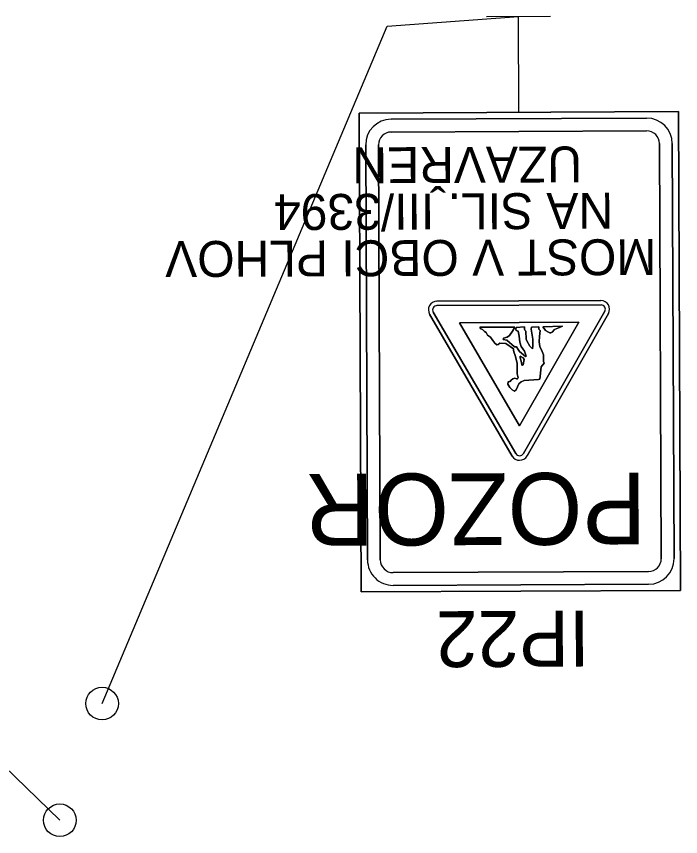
# Model space of a CAD drawing. Extents: x -688893 to -679983, y -1088371 to -1075771.
# Drawn here: x -686022 to -685398, y -1077861 to -1077090 of the extents above; entities that cross this region are included whole.
import ezdxf

# ---------------------------------------------------------------- set-up
doc = ezdxf.new("R2010")
doc.units = 0
for name, color, linetype in [('SDZ', 7, 'Continuous'), ('SDZ ozn', 7, 'Continuous'), ('SDZ plochy', 7, 'Continuous'), ('SDZ symbol', 7, 'Continuous')]:
    doc.layers.add(name, color=color, linetype=linetype)

msp = doc.modelspace()

# ---------------------------------------------------------------- linework, layer by layer
at = {"layer": 'SDZ'}
for p, q in [((-685520.53, -1077089.96), (-685580.53, -1077090.22)), ((-685550.14, -1077180.09), (-685550.53, -1077090.09)), ((-685700.14, -1077180.75), (-685400.14, -1077179.43)), ((-685698.17, -1077630.74), (-685700.14, -1077180.75)), ((-685670.11, -1077186.62), (-685430.11, -1077185.57)), ((-685400.14, -1077179.43), (-685398.17, -1077629.43)), ((-685670.06, -1077198.62), (-685430.06, -1077197.57)), ((-685692.3, -1077600.72), (-685694.01, -1077210.72)), ((-685680.3, -1077600.66), (-685682.01, -1077210.67)), ((-685418.01, -1077209.51), (-685416.3, -1077599.51)), ((-685406.01, -1077209.46), (-685404.3, -1077599.46)), ((-685472.92, -1077361.01), (-685627.1, -1077361.69)), ((-685473.01, -1077356.96), (-685627.05, -1077357.64)), ((-685556.41, -1077503.05), (-685634.01, -1077369.81)), ((-685630.58, -1077367.78), (-685552.91, -1077500.78)), ((-685545.89, -1077500.74), (-685469.39, -1077367.07)), ((-685465.94, -1077369.08), (-685542.37, -1077502.99)), ((-685493.85, -1077377.3), (-685606.03, -1077377.79)), ((-685606.03, -1077377.79), (-685549.52, -1077474.55)), ((-685549.52, -1077474.55), (-685493.85, -1077377.3)), ((-685553.97, -1077382.02), (-685586.78, -1077381.96)), ((-685586.78, -1077381.96), (-685585.96, -1077383.58)), ((-685585.96, -1077383.58), (-685584.13, -1077384.18)), ((-685584.13, -1077384.18), (-685582.51, -1077385.99)), ((-685582.51, -1077385.99), (-685580.88, -1077387)), ((-685558.8, -1077389.94), (-685556.18, -1077385.88)), ((-685556.18, -1077385.88), (-685553.97, -1077382.02)), ((-685552.55, -1077382.22), (-685552.95, -1077383.84)), ((-685552.95, -1077383.84), (-685552.74, -1077385.05)), ((-685552.74, -1077385.05), (-685550.71, -1077385.85)), ((-685544.86, -1077381.58), (-685552.55, -1077382.22)), ((-685550.71, -1077385.85), (-685549.88, -1077390.51)), ((-685544.85, -1077383.8), (-685544.86, -1077381.58)), ((-685544.64, -1077384.82), (-685544.85, -1077383.8)), ((-685543.42, -1077385.82), (-685544.64, -1077384.82)), ((-685543.39, -1077393.32), (-685543.42, -1077385.82)), ((-685538.18, -1077381.95), (-685538.57, -1077383.78)), ((-685538.57, -1077383.78), (-685536.91, -1077393.29)), ((-685531.49, -1077381.72), (-685538.18, -1077381.95)), ((-685531.28, -1077383.74), (-685531.49, -1077381.72)), ((-685530.06, -1077384.95), (-685531.28, -1077383.74)), ((-685530.85, -1077390.63), (-685530.06, -1077384.95)), ((-685509.02, -1077381.01), (-685527.65, -1077381.5)), ((-685527.65, -1077381.5), (-685526.43, -1077383.12)), ((-685526.43, -1077383.12), (-685525, -1077385.13)), ((-685525, -1077385.13), (-685522.16, -1077386.54)), ((-685518.92, -1077386.73), (-685516.5, -1077384.08)), ((-685516.5, -1077384.08), (-685513.47, -1077382.86)), ((-685513.47, -1077382.86), (-685509.02, -1077381.01)), ((-685580.88, -1077387), (-685579.45, -1077389.42)), ((-685579.45, -1077389.42), (-685576.81, -1077391.44)), ((-685576.81, -1077391.44), (-685574.57, -1077394.46)), ((-685564.85, -1077393.61), (-685564.46, -1077392.19)), ((-685561.41, -1077394.2), (-685564.85, -1077393.61)), ((-685564.46, -1077392.19), (-685561.22, -1077391.37)), ((-685554.09, -1077400.45), (-685561.41, -1077394.2)), ((-685561.22, -1077391.37), (-685558.8, -1077389.94)), ((-685549.88, -1077390.51), (-685549.25, -1077395.97)), ((-685542.57, -1077394.73), (-685543.39, -1077393.32)), ((-685536.91, -1077393.29), (-685536.88, -1077399.36)), ((-685531.03, -1077395.69), (-685530.85, -1077390.63)), ((-685522.16, -1077386.54), (-685521.14, -1077387.14)), ((-685521.14, -1077387.14), (-685519.93, -1077387.14)), ((-685519.93, -1077387.14), (-685518.92, -1077386.73)), ((-685574.57, -1077394.46), (-685572.53, -1077397.09)), ((-685572.53, -1077397.09), (-685570.91, -1077398.7)), ((-685570.91, -1077398.7), (-685569.69, -1077398.29)), ((-685569.69, -1077398.29), (-685568.08, -1077396.87)), ((-685568.08, -1077396.87), (-685562.41, -1077397.25)), ((-685562.41, -1077397.25), (-685555.1, -1077402.28)), ((-685552.47, -1077400.44), (-685554.09, -1077400.45)), ((-685550.64, -1077402.86), (-685552.47, -1077400.44)), ((-685549.25, -1077395.97), (-685547.82, -1077400.22)), ((-685547.82, -1077400.22), (-685544.76, -1077404.66)), ((-685539.72, -1077399.78), (-685542.57, -1077394.73)), ((-685537.28, -1077402.4), (-685539.72, -1077399.78)), ((-685536.88, -1077399.36), (-685537.28, -1077402.4)), ((-685530.4, -1077400.14), (-685531.03, -1077395.69)), ((-685528.35, -1077404.99), (-685530.4, -1077400.14)), ((-685555.1, -1077402.28), (-685555.29, -1077403.49)), ((-685555.29, -1077403.49), (-685554.68, -1077405.11)), ((-685554.68, -1077405.11), (-685553.45, -1077408.55)), ((-685553.45, -1077408.55), (-685551.8, -1077415.83)), ((-685549.42, -1077404.68), (-685550.64, -1077402.86)), ((-685543.72, -1077409.52), (-685549.42, -1077404.68)), ((-685548.79, -1077409.13), (-685548.78, -1077410.75)), ((-685546.15, -1077410.74), (-685548.79, -1077409.13)), ((-685544.76, -1077404.66), (-685543.32, -1077409.11)), ((-685543.32, -1077409.11), (-685543.72, -1077409.52)), ((-685526.92, -1077408.03), (-685528.35, -1077404.99)), ((-685527.1, -1077414.3), (-685526.92, -1077408.03)), ((-685551.8, -1077415.83), (-685551.57, -1077422.11)), ((-685548.78, -1077410.75), (-685547.96, -1077413.99)), ((-685547.96, -1077413.99), (-685547.34, -1077417.03)), ((-685547.34, -1077417.03), (-685546.73, -1077418.04)), ((-685545.13, -1077412.36), (-685546.15, -1077410.74)), ((-685545.92, -1077417.42), (-685545.33, -1077413.78)), ((-685545.33, -1077413.78), (-685545.13, -1077412.36)), ((-685529.1, -1077419.17), (-685526.28, -1077415.72)), ((-685526.28, -1077415.72), (-685527.1, -1077414.3)), ((-685551.57, -1077422.11), (-685551.55, -1077425.95)), ((-685546.73, -1077418.04), (-685545.92, -1077417.42)), ((-685530.27, -1077430.72), (-685529.1, -1077419.17)), ((-685557.2, -1077431.65), (-685558.2, -1077433.07)), ((-685555.78, -1077430.43), (-685557.2, -1077431.65)), ((-685553.96, -1077430.01), (-685555.78, -1077430.43)), ((-685552.34, -1077430.61), (-685553.96, -1077430.01)), ((-685551.53, -1077430.61), (-685552.34, -1077430.61)), ((-685551.55, -1077425.95), (-685551.13, -1077428.38)), ((-685550.73, -1077429.39), (-685551.53, -1077430.61)), ((-685551.13, -1077428.38), (-685550.73, -1077429.39)), ((-685548.08, -1077433.23), (-685545.25, -1077432.2)), ((-685545.25, -1077432.2), (-685531.68, -1077431.13)), ((-685531.68, -1077431.13), (-685530.27, -1077430.72)), ((-685560.23, -1077433.48), (-685560.42, -1077435.51)), ((-685560.42, -1077435.51), (-685558.58, -1077438.54)), ((-685559.22, -1077432.87), (-685560.23, -1077433.48)), ((-685558.2, -1077433.07), (-685559.22, -1077432.87)), ((-685558.58, -1077438.54), (-685556.34, -1077440.96)), ((-685552.7, -1077440.94), (-685551.29, -1077438.1)), ((-685551.29, -1077438.1), (-685550.09, -1077435.06)), ((-685550.09, -1077435.06), (-685548.08, -1077433.23)), ((-685556.34, -1077440.96), (-685554.32, -1077441.96)), ((-685554.32, -1077441.96), (-685552.7, -1077440.94)), ((-685545.96, -1077500.85), (-685545.96, -1077500.85)), ((-685556.48, -1077502.93), (-685556.48, -1077502.93)), ((-685428.25, -1077611.56), (-685668.25, -1077612.61)), ((-685428.2, -1077623.56), (-685668.19, -1077624.61)), ((-685398.17, -1077629.43), (-685698.17, -1077630.74))]:
    msp.add_line(p, q, dxfattribs=at)
for points in [[(-685941.66, -1077735.65), (-685673.9, -1077099.13), (-685550.53, -1077090.09)], [(-685981.36, -1077845.3), (-686201.95, -1077631.56), (-686300.88, -1077632.7)]]:
    msp.add_lwpolyline(points, dxfattribs=at)
for centre in [(-685941.66, -1077735.65), (-685981.36, -1077845.3)]:
    msp.add_circle(centre, 15.36, dxfattribs=at)
for centre, radius, start, end in [((-685430.01, -1077209.57), 24, 0.25087, 90.25087), ((-685670.01, -1077210.62), 24, 90.25087, 180.25087), ((-685670.01, -1077210.62), 12, 90.25087, 180.25087), ((-685430.01, -1077209.57), 12, 0.25087, 90.25087), ((-685627.02, -1077365.74), 8.1, 90.25087, 210.21996), ((-685627.08, -1077365.74), 4.05, 90.25087, 210.28517), ((-685472.97, -1077365.06), 8.1, 330.28177, 90.25087), ((-685472.91, -1077365.06), 4.05, 330.21657, 90.25087), ((-685549.41, -1077498.73), 4.05, 210.28517, 330.21657), ((-685549.41, -1077498.97), 8.1, 210.21996, 330.28177), ((-685668.3, -1077600.61), 24, 180.25087, 270.25087), ((-685668.3, -1077600.61), 12, 180.25087, 270.25087), ((-685428.3, -1077599.56), 12, 270.25087, 0.25087), ((-685428.3, -1077599.56), 24, 270.25087, 0.25087)]:
    msp.add_arc(centre, radius, start, end, dxfattribs=at)
at = {"layer": 'SDZ plochy'}
for p, q in [((-685400.14, -1077179.43), (-685700.14, -1077180.75)), ((-685700.14, -1077180.75), (-685698.17, -1077630.74)), ((-685430.11, -1077185.57), (-685670.11, -1077186.62)), ((-685670.11, -1077186.62), (-685430.11, -1077185.57)), ((-685398.17, -1077629.43), (-685400.14, -1077179.43)), ((-685670.06, -1077198.62), (-685430.06, -1077197.57)), ((-685430.06, -1077197.57), (-685670.06, -1077198.62)), ((-685694.01, -1077210.72), (-685692.3, -1077600.72)), ((-685692.3, -1077600.72), (-685694.01, -1077210.72)), ((-685680.3, -1077600.66), (-685682.01, -1077210.67)), ((-685682.01, -1077210.67), (-685680.3, -1077600.66)), ((-685418.01, -1077209.51), (-685416.3, -1077599.51)), ((-685416.3, -1077599.51), (-685418.01, -1077209.51)), ((-685404.3, -1077599.46), (-685406.01, -1077209.46)), ((-685406.01, -1077209.46), (-685404.3, -1077599.46)), ((-685472.92, -1077361.01), (-685627.1, -1077361.69)), ((-685627.1, -1077361.69), (-685472.92, -1077361.01)), ((-685627.05, -1077357.64), (-685473.01, -1077356.96)), ((-685473.01, -1077356.96), (-685627.05, -1077357.64)), ((-685556.41, -1077503.05), (-685634.01, -1077369.81)), ((-685634.01, -1077369.81), (-685556.41, -1077503.05)), ((-685630.58, -1077367.78), (-685552.91, -1077500.78)), ((-685552.91, -1077500.78), (-685630.58, -1077367.78)), ((-685545.89, -1077500.74), (-685469.39, -1077367.07)), ((-685469.39, -1077367.07), (-685545.89, -1077500.74)), ((-685465.94, -1077369.08), (-685542.37, -1077502.99)), ((-685542.37, -1077502.99), (-685465.94, -1077369.08)), ((-685606.03, -1077377.79), (-685493.85, -1077377.3)), ((-685493.85, -1077377.3), (-685606.03, -1077377.79)), ((-685549.52, -1077474.55), (-685606.03, -1077377.79)), ((-685606.03, -1077377.79), (-685549.52, -1077474.55)), ((-685493.85, -1077377.3), (-685549.52, -1077474.55)), ((-685549.52, -1077474.55), (-685493.85, -1077377.3)), ((-685553.97, -1077382.02), (-685586.78, -1077381.96)), ((-685586.78, -1077381.96), (-685585.96, -1077383.58)), ((-685585.96, -1077383.58), (-685586.78, -1077381.96)), ((-685586.78, -1077381.96), (-685553.97, -1077382.02)), ((-685585.96, -1077383.58), (-685584.13, -1077384.18)), ((-685584.13, -1077384.18), (-685585.96, -1077383.58)), ((-685584.13, -1077384.18), (-685582.51, -1077385.99)), ((-685582.51, -1077385.99), (-685584.13, -1077384.18)), ((-685582.51, -1077385.99), (-685580.88, -1077387)), ((-685580.88, -1077387), (-685582.51, -1077385.99)), ((-685558.8, -1077389.94), (-685556.18, -1077385.88)), ((-685556.18, -1077385.88), (-685558.8, -1077389.94)), ((-685556.18, -1077385.88), (-685553.97, -1077382.02)), ((-685553.97, -1077382.02), (-685556.18, -1077385.88)), ((-685552.55, -1077382.22), (-685552.95, -1077383.84)), ((-685552.95, -1077383.84), (-685552.55, -1077382.22)), ((-685552.95, -1077383.84), (-685552.74, -1077385.05)), ((-685552.74, -1077385.05), (-685552.95, -1077383.84)), ((-685552.74, -1077385.05), (-685550.71, -1077385.85)), ((-685550.71, -1077385.85), (-685552.74, -1077385.05)), ((-685544.86, -1077381.58), (-685552.55, -1077382.22)), ((-685552.55, -1077382.22), (-685544.86, -1077381.58)), ((-685550.71, -1077385.85), (-685549.88, -1077390.51)), ((-685549.88, -1077390.51), (-685550.71, -1077385.85)), ((-685544.85, -1077383.8), (-685544.86, -1077381.58)), ((-685544.86, -1077381.58), (-685544.85, -1077383.8)), ((-685544.64, -1077384.82), (-685544.85, -1077383.8)), ((-685544.85, -1077383.8), (-685544.64, -1077384.82)), ((-685543.42, -1077385.82), (-685544.64, -1077384.82)), ((-685544.64, -1077384.82), (-685543.42, -1077385.82)), ((-685543.39, -1077393.32), (-685543.42, -1077385.82)), ((-685543.42, -1077385.82), (-685543.39, -1077393.32)), ((-685538.18, -1077381.95), (-685538.57, -1077383.78)), ((-685538.57, -1077383.78), (-685538.18, -1077381.95)), ((-685538.57, -1077383.78), (-685536.91, -1077393.29)), ((-685536.91, -1077393.29), (-685538.57, -1077383.78)), ((-685531.49, -1077381.72), (-685538.18, -1077381.95)), ((-685538.18, -1077381.95), (-685531.49, -1077381.72)), ((-685531.28, -1077383.74), (-685531.49, -1077381.72)), ((-685531.49, -1077381.72), (-685531.28, -1077383.74)), ((-685530.06, -1077384.95), (-685531.28, -1077383.74)), ((-685531.28, -1077383.74), (-685530.06, -1077384.95)), ((-685530.85, -1077390.63), (-685530.06, -1077384.95)), ((-685530.06, -1077384.95), (-685530.85, -1077390.63)), ((-685509.02, -1077381.01), (-685527.65, -1077381.5)), ((-685527.65, -1077381.5), (-685509.02, -1077381.01)), ((-685527.65, -1077381.5), (-685526.43, -1077383.12)), ((-685526.43, -1077383.12), (-685527.65, -1077381.5)), ((-685526.43, -1077383.12), (-685525, -1077385.13)), ((-685525, -1077385.13), (-685526.43, -1077383.12)), ((-685525, -1077385.13), (-685522.16, -1077386.54)), ((-685522.16, -1077386.54), (-685525, -1077385.13)), ((-685518.92, -1077386.73), (-685516.5, -1077384.08)), ((-685516.5, -1077384.08), (-685518.92, -1077386.73)), ((-685516.5, -1077384.08), (-685513.47, -1077382.86)), ((-685513.47, -1077382.86), (-685516.5, -1077384.08)), ((-685513.47, -1077382.86), (-685509.02, -1077381.01)), ((-685509.02, -1077381.01), (-685513.47, -1077382.86)), ((-685580.88, -1077387), (-685579.45, -1077389.42)), ((-685579.45, -1077389.42), (-685580.88, -1077387)), ((-685579.45, -1077389.42), (-685576.81, -1077391.44)), ((-685576.81, -1077391.44), (-685579.45, -1077389.42)), ((-685576.81, -1077391.44), (-685574.57, -1077394.46)), ((-685574.57, -1077394.46), (-685576.81, -1077391.44)), ((-685564.85, -1077393.61), (-685564.46, -1077392.19)), ((-685564.46, -1077392.19), (-685564.85, -1077393.61)), ((-685561.41, -1077394.2), (-685564.85, -1077393.61)), ((-685564.85, -1077393.61), (-685561.41, -1077394.2)), ((-685564.46, -1077392.19), (-685561.22, -1077391.37)), ((-685561.22, -1077391.37), (-685564.46, -1077392.19)), ((-685554.09, -1077400.45), (-685561.41, -1077394.2)), ((-685561.41, -1077394.2), (-685554.09, -1077400.45)), ((-685561.22, -1077391.37), (-685558.8, -1077389.94)), ((-685558.8, -1077389.94), (-685561.22, -1077391.37)), ((-685549.88, -1077390.51), (-685549.25, -1077395.97)), ((-685549.25, -1077395.97), (-685549.88, -1077390.51)), ((-685542.57, -1077394.73), (-685543.39, -1077393.32)), ((-685543.39, -1077393.32), (-685542.57, -1077394.73)), ((-685536.91, -1077393.29), (-685536.88, -1077399.36)), ((-685536.88, -1077399.36), (-685536.91, -1077393.29)), ((-685531.03, -1077395.69), (-685530.85, -1077390.63)), ((-685530.85, -1077390.63), (-685531.03, -1077395.69)), ((-685522.16, -1077386.54), (-685521.14, -1077387.14)), ((-685521.14, -1077387.14), (-685522.16, -1077386.54)), ((-685521.14, -1077387.14), (-685519.93, -1077387.14)), ((-685519.93, -1077387.14), (-685521.14, -1077387.14)), ((-685519.93, -1077387.14), (-685518.92, -1077386.73)), ((-685518.92, -1077386.73), (-685519.93, -1077387.14)), ((-685574.57, -1077394.46), (-685572.53, -1077397.09)), ((-685572.53, -1077397.09), (-685574.57, -1077394.46)), ((-685572.53, -1077397.09), (-685570.91, -1077398.7)), ((-685570.91, -1077398.7), (-685572.53, -1077397.09)), ((-685570.91, -1077398.7), (-685569.69, -1077398.29)), ((-685569.69, -1077398.29), (-685570.91, -1077398.7)), ((-685569.69, -1077398.29), (-685568.08, -1077396.87)), ((-685568.08, -1077396.87), (-685569.69, -1077398.29)), ((-685568.08, -1077396.87), (-685562.41, -1077397.25)), ((-685562.41, -1077397.25), (-685568.08, -1077396.87)), ((-685562.41, -1077397.25), (-685555.1, -1077402.28)), ((-685555.1, -1077402.28), (-685562.41, -1077397.25)), ((-685552.47, -1077400.44), (-685554.09, -1077400.45)), ((-685554.09, -1077400.45), (-685552.47, -1077400.44)), ((-685550.64, -1077402.86), (-685552.47, -1077400.44)), ((-685552.47, -1077400.44), (-685550.64, -1077402.86)), ((-685549.25, -1077395.97), (-685547.82, -1077400.22)), ((-685547.82, -1077400.22), (-685549.25, -1077395.97)), ((-685547.82, -1077400.22), (-685544.76, -1077404.66)), ((-685544.76, -1077404.66), (-685547.82, -1077400.22)), ((-685539.72, -1077399.78), (-685542.57, -1077394.73)), ((-685542.57, -1077394.73), (-685539.72, -1077399.78)), ((-685537.28, -1077402.4), (-685539.72, -1077399.78)), ((-685539.72, -1077399.78), (-685537.28, -1077402.4)), ((-685536.88, -1077399.36), (-685537.28, -1077402.4)), ((-685537.28, -1077402.4), (-685536.88, -1077399.36)), ((-685530.4, -1077400.14), (-685531.03, -1077395.69)), ((-685531.03, -1077395.69), (-685530.4, -1077400.14)), ((-685528.35, -1077404.99), (-685530.4, -1077400.14)), ((-685530.4, -1077400.14), (-685528.35, -1077404.99)), ((-685555.1, -1077402.28), (-685555.29, -1077403.49)), ((-685555.29, -1077403.49), (-685555.1, -1077402.28)), ((-685555.29, -1077403.49), (-685554.68, -1077405.11)), ((-685554.68, -1077405.11), (-685555.29, -1077403.49)), ((-685554.68, -1077405.11), (-685553.45, -1077408.55)), ((-685553.45, -1077408.55), (-685554.68, -1077405.11)), ((-685553.45, -1077408.55), (-685551.8, -1077415.83)), ((-685551.8, -1077415.83), (-685553.45, -1077408.55)), ((-685549.42, -1077404.68), (-685550.64, -1077402.86)), ((-685550.64, -1077402.86), (-685549.42, -1077404.68)), ((-685543.72, -1077409.52), (-685549.42, -1077404.68)), ((-685549.42, -1077404.68), (-685543.72, -1077409.52)), ((-685548.78, -1077410.75), (-685548.79, -1077409.13)), ((-685548.79, -1077409.13), (-685546.15, -1077410.74)), ((-685548.79, -1077409.13), (-685548.78, -1077410.75)), ((-685546.15, -1077410.74), (-685548.79, -1077409.13)), ((-685544.76, -1077404.66), (-685543.32, -1077409.11)), ((-685543.32, -1077409.11), (-685544.76, -1077404.66)), ((-685543.32, -1077409.11), (-685543.72, -1077409.52)), ((-685543.72, -1077409.52), (-685543.32, -1077409.11)), ((-685526.92, -1077408.03), (-685528.35, -1077404.99)), ((-685528.35, -1077404.99), (-685526.92, -1077408.03)), ((-685527.1, -1077414.3), (-685526.92, -1077408.03)), ((-685526.92, -1077408.03), (-685527.1, -1077414.3)), ((-685551.8, -1077415.83), (-685551.57, -1077422.11)), ((-685551.57, -1077422.11), (-685551.8, -1077415.83)), ((-685547.96, -1077413.99), (-685548.78, -1077410.75)), ((-685548.78, -1077410.75), (-685547.96, -1077413.99)), ((-685547.34, -1077417.03), (-685547.96, -1077413.99)), ((-685547.96, -1077413.99), (-685547.34, -1077417.03)), ((-685546.73, -1077418.04), (-685547.34, -1077417.03)), ((-685547.34, -1077417.03), (-685546.73, -1077418.04)), ((-685546.15, -1077410.74), (-685545.13, -1077412.36)), ((-685545.13, -1077412.36), (-685546.15, -1077410.74)), ((-685545.33, -1077413.78), (-685545.92, -1077417.42)), ((-685545.92, -1077417.42), (-685545.33, -1077413.78)), ((-685545.13, -1077412.36), (-685545.33, -1077413.78)), ((-685545.33, -1077413.78), (-685545.13, -1077412.36)), ((-685529.1, -1077419.17), (-685526.28, -1077415.72)), ((-685526.28, -1077415.72), (-685529.1, -1077419.17)), ((-685526.28, -1077415.72), (-685527.1, -1077414.3)), ((-685527.1, -1077414.3), (-685526.28, -1077415.72)), ((-685551.57, -1077422.11), (-685551.55, -1077425.95)), ((-685551.55, -1077425.95), (-685551.57, -1077422.11)), ((-685545.92, -1077417.42), (-685546.73, -1077418.04)), ((-685546.73, -1077418.04), (-685545.92, -1077417.42)), ((-685530.27, -1077430.72), (-685529.1, -1077419.17)), ((-685529.1, -1077419.17), (-685530.27, -1077430.72)), ((-685557.2, -1077431.65), (-685558.2, -1077433.07)), ((-685558.2, -1077433.07), (-685557.2, -1077431.65)), ((-685555.78, -1077430.43), (-685557.2, -1077431.65)), ((-685557.2, -1077431.65), (-685555.78, -1077430.43)), ((-685553.96, -1077430.01), (-685555.78, -1077430.43)), ((-685555.78, -1077430.43), (-685553.96, -1077430.01)), ((-685552.34, -1077430.61), (-685553.96, -1077430.01)), ((-685553.96, -1077430.01), (-685552.34, -1077430.61)), ((-685551.53, -1077430.61), (-685552.34, -1077430.61)), ((-685552.34, -1077430.61), (-685551.53, -1077430.61)), ((-685551.55, -1077425.95), (-685551.13, -1077428.38)), ((-685551.13, -1077428.38), (-685551.55, -1077425.95)), ((-685550.73, -1077429.39), (-685551.53, -1077430.61)), ((-685551.53, -1077430.61), (-685550.73, -1077429.39)), ((-685551.13, -1077428.38), (-685550.73, -1077429.39)), ((-685550.73, -1077429.39), (-685551.13, -1077428.38)), ((-685548.08, -1077433.23), (-685545.25, -1077432.2)), ((-685545.25, -1077432.2), (-685548.08, -1077433.23)), ((-685545.25, -1077432.2), (-685531.68, -1077431.13)), ((-685531.68, -1077431.13), (-685545.25, -1077432.2)), ((-685531.68, -1077431.13), (-685530.27, -1077430.72)), ((-685530.27, -1077430.72), (-685531.68, -1077431.13)), ((-685560.23, -1077433.48), (-685560.42, -1077435.51)), ((-685560.42, -1077435.51), (-685560.23, -1077433.48)), ((-685560.42, -1077435.51), (-685558.58, -1077438.54)), ((-685558.58, -1077438.54), (-685560.42, -1077435.51)), ((-685559.22, -1077432.87), (-685560.23, -1077433.48)), ((-685560.23, -1077433.48), (-685559.22, -1077432.87)), ((-685558.2, -1077433.07), (-685559.22, -1077432.87)), ((-685559.22, -1077432.87), (-685558.2, -1077433.07)), ((-685558.58, -1077438.54), (-685556.34, -1077440.96)), ((-685556.34, -1077440.96), (-685558.58, -1077438.54)), ((-685552.7, -1077440.94), (-685551.29, -1077438.1)), ((-685551.29, -1077438.1), (-685552.7, -1077440.94)), ((-685551.29, -1077438.1), (-685550.09, -1077435.06)), ((-685550.09, -1077435.06), (-685551.29, -1077438.1)), ((-685550.09, -1077435.06), (-685548.08, -1077433.23)), ((-685548.08, -1077433.23), (-685550.09, -1077435.06)), ((-685556.34, -1077440.96), (-685554.32, -1077441.96)), ((-685554.32, -1077441.96), (-685556.34, -1077440.96)), ((-685554.32, -1077441.96), (-685552.7, -1077440.94)), ((-685552.7, -1077440.94), (-685554.32, -1077441.96)), ((-685428.25, -1077611.56), (-685668.25, -1077612.61)), ((-685668.25, -1077612.61), (-685428.25, -1077611.56)), ((-685668.19, -1077624.61), (-685428.2, -1077623.56)), ((-685428.2, -1077623.56), (-685668.19, -1077624.61)), ((-685698.17, -1077630.74), (-685398.17, -1077629.43))]:
    msp.add_line(p, q, dxfattribs=at)
for centre, radius, start, end in [((-685430.01, -1077209.57), 24, 0.25087, 90.25087), ((-685430.01, -1077209.57), 24, 0.25087, 90.25087), ((-685670.01, -1077210.62), 24, 90.25087, 180.25087), ((-685670.01, -1077210.62), 24, 90.25087, 180.25087), ((-685670.01, -1077210.62), 12, 90.25087, 180.25087), ((-685670.01, -1077210.62), 12, 90.25087, 180.25087), ((-685430.01, -1077209.57), 12, 0.25087, 90.25087), ((-685430.01, -1077209.57), 12, 0.25087, 90.25087), ((-685627.02, -1077365.74), 8.1, 90.25087, 210.21996), ((-685627.02, -1077365.74), 8.1, 90.25087, 210.21996), ((-685627.08, -1077365.74), 4.05, 90.25087, 210.28517), ((-685627.08, -1077365.74), 4.05, 90.25087, 210.28517), ((-685472.97, -1077365.06), 8.1, 330.28177, 90.25087), ((-685472.97, -1077365.06), 8.1, 330.28177, 90.25087), ((-685472.91, -1077365.06), 4.05, 330.21657, 90.25087), ((-685472.91, -1077365.06), 4.05, 330.21657, 90.25087), ((-685549.41, -1077498.73), 4.05, 210.28517, 330.21657), ((-685549.41, -1077498.73), 4.05, 210.28517, 330.21657), ((-685549.41, -1077498.97), 8.1, 210.21996, 330.28177), ((-685549.41, -1077498.97), 8.1, 210.21996, 330.28177), ((-685668.3, -1077600.61), 24, 180.25087, 270.25087), ((-685668.3, -1077600.61), 24, 180.25087, 270.25087), ((-685668.3, -1077600.61), 12, 180.25087, 270.25087), ((-685668.3, -1077600.61), 12, 180.25087, 270.25087), ((-685428.3, -1077599.56), 12, 270.25087, 0.25087), ((-685428.3, -1077599.56), 12, 270.25087, 0.25087), ((-685428.3, -1077599.56), 24, 270.25087, 0.25087), ((-685428.3, -1077599.56), 24, 270.25087, 0.25087)]:
    msp.add_arc(centre, radius, start, end, dxfattribs=at)

# ---------------------------------------------------------------- texts
at = {"layer": 'SDZ ozn'}
msp.add_text('IP22', height=52.5, rotation=180.25087, dxfattribs=at).set_placement((-685483.68, -1077648.29))
at = {"layer": 'SDZ symbol'}
for s, height, p in [('UZAVŘEN', 33.75, (-685490.85, -1077212.11)), ('NA SIL. III/3394', 33.75, (-685461.6, -1077255.66)), ('MOST V OBCI PLHOV', 33.75, (-685421.07, -1077299.16)), ('POZOR', 67.5, (-685430.46, -1077518.57))]:
    msp.add_text(s, height=height, rotation=180.25087, dxfattribs=at).set_placement(p)

doc.saveas('drawing.dxf')
